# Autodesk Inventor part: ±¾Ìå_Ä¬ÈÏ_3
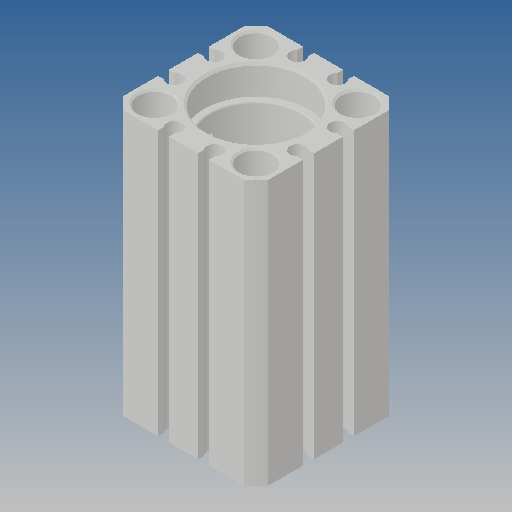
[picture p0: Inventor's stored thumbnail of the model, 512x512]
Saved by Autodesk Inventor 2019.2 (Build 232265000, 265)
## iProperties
Created: 2013-03
Part Number: ±¾Ìå_Ä¬ÈÏ_3
Material: Ogólny
Document SubType Name: Modeling
Designer: CADENGINEERING4
Density: 1 g/cm^3
Appearance: Domyślna
Author: CADENGINEERING4
Revision Number: ÈÎºÎ
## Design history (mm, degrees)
feature "NONE"
node "Bryła1"
